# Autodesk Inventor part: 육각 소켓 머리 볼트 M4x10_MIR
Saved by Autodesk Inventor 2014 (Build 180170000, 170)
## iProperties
Created: 2024-05
Part Number: 육각 소켓 머리 볼트 M4x10_MIR
Material: 일반
Document SubType Name: Modeling
Designer: dg
Density: 1 g/cm^3
Appearance: 기본값
Author: dg
Author: jhkim
Description: 6각머리 태핑 나사
Creation Date: 2024-05-07
Sending System: Autodesk Inventor 2025
Preprocessor: ST-DEVELOPER v20
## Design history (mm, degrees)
derived "육각 소켓 머리 볼트 M4x10.ipt"
feature "Solid1::육각 소켓 머리 볼트 M4x10.ipt" dims "d0" = 10
tag "피쳐 태그1"
node "솔리드1"
